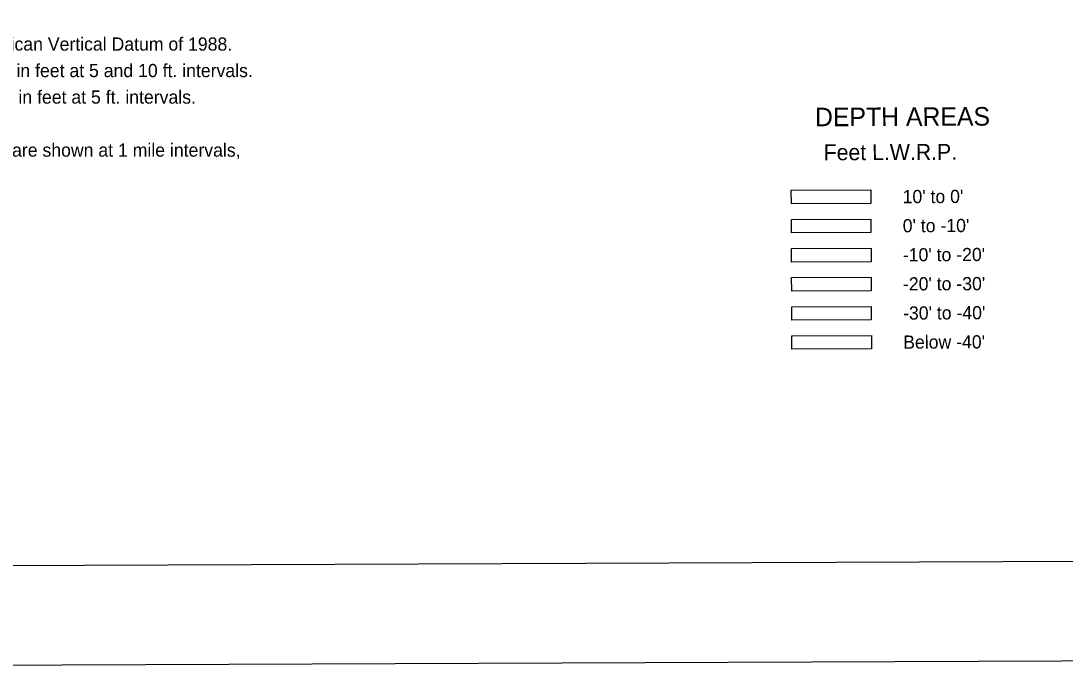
# Model space of a CAD drawing. Extents: x 3405885 to 3443815, y 558517 to 583997.
# Drawn here: x 3413116 to 3419685, y 559100 to 563176 of the extents above; entities that cross this region are included whole.
import ezdxf

# ---------------------------------------------------------------- set-up
doc = ezdxf.new("R2010")
doc.units = 0
for name, color, linetype in [('G-ANNO-NPLT', 7, 'Continuous'), ('V-ANNO-NOTE', 7, 'Continuous'), ('V-ANNO-SYMB', 7, 'Continuous'), ('V-TOPO-DPTH', 7, 'Continuous')]:
    doc.layers.add(name, color=color, linetype=linetype)

msp = doc.modelspace()

# ---------------------------------------------------------------- linework, layer by layer
at = {"layer": 'G-ANNO-NPLT'}
msp.add_lwpolyline([(3406564.9, 559100.1), (3443231.3, 559246.8), (3443134.6, 583413.3), (3406468.2, 583266.6)], close=True, dxfattribs=at)
at = {"layer": 'V-ANNO-SYMB'}
msp.add_lwpolyline([(3409312.5, 559736.2), (3442395.5, 559868.5), (3442303.8, 582784.9), (3409220.9, 582652.6), (3409312.5, 559736.2)], dxfattribs=at)
at = {"layer": 'V-TOPO-DPTH'}
for points in [[(3417962.4, 562110.8), (3418462.3, 562112.8), (3418462.7, 562027.8), (3417962.7, 562025.8)], [(3417963.1, 561927.8), (3418463.1, 561929.8), (3418463.4, 561844.8), (3417963.4, 561842.8)], [(3417963.8, 561744.8), (3418463.8, 561746.8), (3418464.2, 561661.9), (3417964.2, 561659.8)], [(3417964.5, 561561.9), (3418464.5, 561563.9), (3418464.9, 561478.9), (3417964.9, 561476.9)], [(3417965.3, 561378.9), (3418465.3, 561380.9), (3418465.6, 561295.9), (3417965.6, 561293.9)], [(3417966, 561195.9), (3418466, 561197.9), (3418466.4, 561112.9), (3417966.4, 561110.9)]]:
    msp.add_lwpolyline(points, close=True, dxfattribs=at)

# ---------------------------------------------------------------- texts
at = {"layer": 'V-ANNO-NOTE'}
for s, p in [('All elevations are expressed in feet and refer to North American Vertical Datum of 1988.', (3410132.7, 562988.9)), ('Contours below Low Water Reference Plane are expressed in feet at 5 and 10 ft. intervals.', (3410132.7, 562822.2)), ('Contours above Low Water Reference Plane are expressed in feet at 5 ft. intervals.', (3410132.7, 562655.5)), ('Distances on Mississippi River above Head of Passes are shown at 1 mile intervals,', (3410382.9, 562322.1))]:
    msp.add_text(s, height=83, rotation=0.00001, dxfattribs=at).set_placement(p)
at = {"layer": 'V-TOPO-DPTH'}
for s, height, rotation, p in [('DEPTH AREAS', 116.7, 0.22921, (3418111.4, 562513.1)), ('Feet L.W.R.P.', 100, 0.2292, (3418166, 562299.2)), ("10' to 0'", 83, 0.2292, (3418662.7, 562029.6)), ("0' to -10'", 83, 0.2292, (3418663.4, 561846.6)), ("-10' to -20'", 83, 0.2292, (3418664.1, 561663.7)), ("-20' to -30'", 83, 0.2292, (3418664.9, 561480.7)), ("-30' to -40'", 83, 0.2292, (3418665.6, 561297.7)), ("Below -40'", 83, 0.2292, (3418666.3, 561114.7))]:
    msp.add_text(s, height=height, rotation=rotation, dxfattribs=at).set_placement(p)

doc.saveas('drawing.dxf')
